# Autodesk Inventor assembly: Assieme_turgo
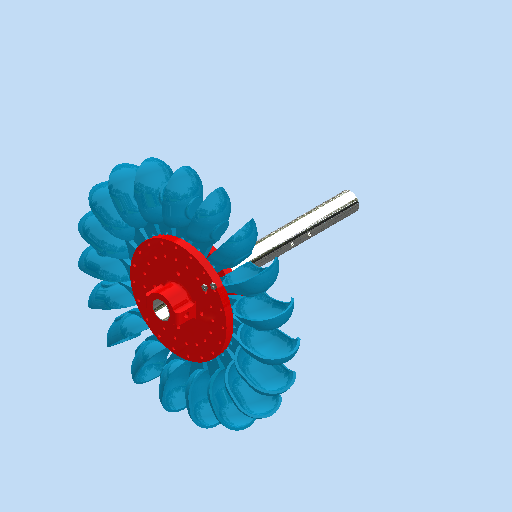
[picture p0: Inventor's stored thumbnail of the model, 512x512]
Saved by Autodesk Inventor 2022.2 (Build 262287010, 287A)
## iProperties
Created: 2025-03
Part Number: Assieme_turgo
Document SubType Name: Assembly
Designer: 18907419
Author: 18907419
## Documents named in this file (6)
- C:\Users\18907419\Desktop\turgo\Assieme_turgo.iam
- C:\Users\18907419\Desktop\turgo\disco.ipt
- C:\Users\18907419\Desktop\turgo\Parte1b.ipt
- C:\Users\18907419\Desktop\turgo\disco_MIR1.ipt
- C:\Users\18907419\Desktop\turgo\AS 1474 - M3(1).ipt
- C:\Users\18907419\Desktop\turgo\albero-20mm.ipt
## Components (24 placed, 5 different names)
1. disco:1
2. Parte1b:1
3. Parte1b:2
4. Parte1b:3
5. Parte1b:4
6. Parte1b:5
7. Parte1b:6
8. Parte1b:7
9. Parte1b:8
10. Parte1b:9
11. Parte1b:10
12. Parte1b:11
13. Parte1b:12
14. Parte1b:13
15. Parte1b:14
16. Parte1b:15
17. Parte1b:16
18. Parte1b:17
19. Parte1b:18
20. Parte1b:19
21. disco_MIR1:1
22. AS 1474 - Metrico M3:1
23. AS 1474 - Metrico M3:2
24. albero-20mm:1
